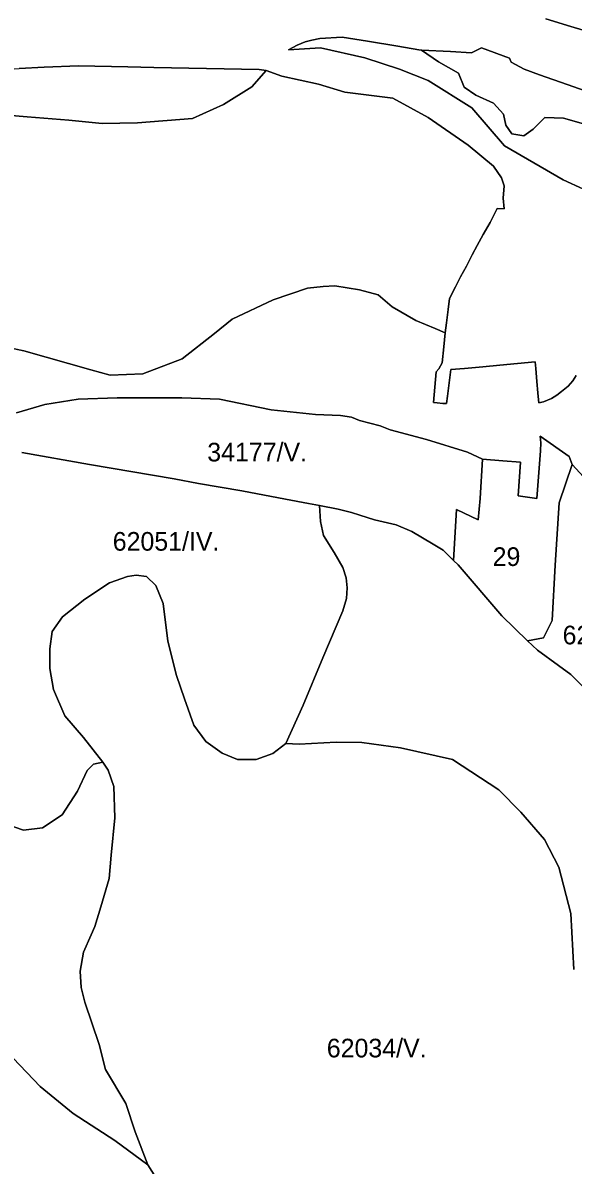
# Model space of a CAD drawing. Extents: x -521621 to -516761, y -1190184 to -1184927.
# Drawn here: x -519109 to -518666, y -1188092 to -1187173 of the extents above; entities that cross this region are included whole.
import ezdxf

# ---------------------------------------------------------------- set-up
doc = ezdxf.new("R2010")
doc.units = 0
doc.layers.add('BPEJ_s', color=7, linetype='Continuous')

msp = doc.modelspace()

# ---------------------------------------------------------------- linework, layer by layer
at = {"layer": 'BPEJ_s'}
for p, q in [((-518688.38, -1187169.96), (-518668.2, -1187176.14)), ((-518668.2, -1187176.14), (-518641.27, -1187184.22)), ((-518888.55, -1187191.16), (-518895.45, -1187195.01)), ((-518882.14, -1187188.59), (-518888.55, -1187191.16)), ((-518876.68, -1187187.14), (-518882.14, -1187188.59)), ((-518870.26, -1187186.02), (-518876.68, -1187187.14)), ((-518852.25, -1187184.81), (-518870.26, -1187186.02)), ((-518831.81, -1187188.13), (-518852.25, -1187184.81)), ((-518807.54, -1187191.97), (-518831.81, -1187188.13)), ((-518790.68, -1187195.03), (-518807.54, -1187191.97)), ((-518895.45, -1187195.01), (-518869.79, -1187193.48)), ((-518869.79, -1187193.48), (-518833.92, -1187201.34)), ((-518833.92, -1187201.34), (-518806.02, -1187210.57)), ((-518788.41, -1187195.16), (-518790.68, -1187195.03)), ((-518765.2, -1187196.45), (-518788.41, -1187195.16)), ((-518748.24, -1187197.55), (-518765.2, -1187196.45)), ((-518740.14, -1187193.42), (-518748.24, -1187197.55)), ((-518717.55, -1187201.72), (-518740.14, -1187193.42)), ((-518716.17, -1187205.03), (-518717.55, -1187201.72)), ((-519092.1, -1187208.96), (-519112.11, -1187210)), ((-519064.5, -1187207.92), (-519092.1, -1187208.96)), ((-519024.83, -1187208.61), (-519064.5, -1187207.92)), ((-519003.79, -1187209.3), (-519024.83, -1187208.61)), ((-518919.06, -1187210.79), (-519003.79, -1187209.3)), ((-518913.41, -1187211.72), (-518919.06, -1187210.79)), ((-518806.02, -1187210.57), (-518783.14, -1187219.65)), ((-518705.68, -1187210.59), (-518716.17, -1187205.03)), ((-518693.5, -1187215.16), (-518705.68, -1187210.59)), ((-518900.96, -1187216.19), (-518913.41, -1187211.72)), ((-518871.22, -1187222.51), (-518900.96, -1187216.19)), ((-518783.14, -1187219.65), (-518747.81, -1187241.68)), ((-518671.13, -1187222.76), (-518693.5, -1187215.16)), ((-518850.19, -1187229.14), (-518871.22, -1187222.51)), ((-518811.5, -1187233.85), (-518850.19, -1187229.14)), ((-518652.08, -1187229.66), (-518671.13, -1187222.76)), ((-518783.14, -1187249.42), (-518811.5, -1187233.85)), ((-518747.81, -1187241.68), (-518721.57, -1187272.27)), ((-518750.97, -1187271.58), (-518783.14, -1187249.42)), ((-518730.57, -1187288.54), (-518750.97, -1187271.58)), ((-518721.57, -1187272.27), (-518674.53, -1187299.62)), ((-518724.01, -1187297.86), (-518730.57, -1187288.54)), ((-518721.97, -1187304.42), (-518724.01, -1187297.86)), ((-518674.53, -1187299.62), (-518631.7, -1187319.15)), ((-518722.65, -1187314.38), (-518721.97, -1187304.42)), ((-518721.97, -1187322.97), (-518722.65, -1187314.38)), ((-518733.28, -1187333.83), (-518727.4, -1187322.52)), ((-518727.4, -1187322.52), (-518721.97, -1187322.97)), ((-518738.7, -1187343.45), (-518733.28, -1187333.83)), ((-518743.56, -1187352.5), (-518738.7, -1187343.45)), ((-518747.52, -1187359.86), (-518743.56, -1187352.5)), ((-518752.27, -1187369.02), (-518747.52, -1187359.86)), ((-518756.96, -1187377.73), (-518752.27, -1187369.02)), ((-518880.2, -1187386.72), (-518867.5, -1187385.44)), ((-518867.5, -1187385.44), (-518858.12, -1187384.95)), ((-518858.12, -1187384.95), (-518838.2, -1187388.01)), ((-518765.94, -1187395.16), (-518761.11, -1187385.61)), ((-518761.11, -1187385.61), (-518756.96, -1187377.73)), ((-518907.72, -1187396.04), (-518880.2, -1187386.72)), ((-518838.2, -1187388.01), (-518823.38, -1187392.1)), ((-518823.38, -1187392.1), (-518812.14, -1187401.82)), ((-518767.05, -1187404.01), (-518765.94, -1187395.16)), ((-518940.75, -1187411.71), (-518907.72, -1187396.04)), ((-518812.14, -1187401.82), (-518792.98, -1187412.81)), ((-518768.43, -1187414.67), (-518767.05, -1187404.01)), ((-518955.14, -1187423.15), (-518940.75, -1187411.71)), ((-518792.98, -1187412.81), (-518777.4, -1187419.2)), ((-519194.34, -1187419.33), (-519108.4, -1187437.13)), ((-518777.4, -1187419.2), (-518769.31, -1187422.77)), ((-518769.31, -1187422.77), (-518770.52, -1187434)), ((-518770.52, -1187434), (-518769.31, -1187422.77)), ((-518769.31, -1187422.77), (-518768.43, -1187414.67)), ((-518980.97, -1187443.48), (-518955.14, -1187423.15)), ((-519108.4, -1187437.13), (-519054.63, -1187452.38)), ((-518770.52, -1187434), (-518771.89, -1187446.71)), ((-518771.89, -1187446.71), (-518770.52, -1187434)), ((-519012.72, -1187455.77), (-518980.97, -1187443.48)), ((-518771.89, -1187446.71), (-518774.35, -1187451.49)), ((-518774.35, -1187451.49), (-518771.89, -1187446.71)), ((-518753.76, -1187451.33), (-518739.1, -1187450.04)), ((-518739.1, -1187450.04), (-518753.76, -1187451.33)), ((-518739.1, -1187450.04), (-518725.3, -1187448.74)), ((-518725.3, -1187448.74), (-518739.1, -1187450.04)), ((-518725.3, -1187448.74), (-518711.06, -1187447.23)), ((-518711.06, -1187447.23), (-518725.3, -1187448.74)), ((-518711.06, -1187447.23), (-518697.05, -1187445.94)), ((-518697.05, -1187445.94), (-518711.06, -1187447.23)), ((-518697.05, -1187445.94), (-518696.4, -1187451.33)), ((-518696.4, -1187451.33), (-518697.05, -1187445.94)), ((-519054.63, -1187452.38), (-519038.97, -1187456.61)), ((-519038.97, -1187456.61), (-519012.72, -1187455.77)), ((-518776.53, -1187454.09), (-518778.1, -1187472.56)), ((-518778.1, -1187472.56), (-518776.53, -1187454.09)), ((-518774.35, -1187451.49), (-518776.53, -1187454.09)), ((-518776.53, -1187454.09), (-518774.35, -1187451.49)), ((-518767.37, -1187473.68), (-518764.76, -1187452.19)), ((-518764.76, -1187452.19), (-518767.37, -1187473.68)), ((-518764.76, -1187452.19), (-518753.76, -1187451.33)), ((-518753.76, -1187451.33), (-518764.76, -1187452.19)), ((-518696.4, -1187451.33), (-518695.54, -1187461.69)), ((-518695.54, -1187461.69), (-518696.4, -1187451.33)), ((-518666.67, -1187461.38), (-518663.99, -1187456.89)), ((-518663.99, -1187456.89), (-518666.67, -1187461.38)), ((-518695.54, -1187461.69), (-518694.83, -1187470.9)), ((-518694.83, -1187470.9), (-518695.54, -1187461.69)), ((-518675.67, -1187469.94), (-518670.34, -1187465.49)), ((-518670.34, -1187465.49), (-518675.67, -1187469.94)), ((-518670.34, -1187465.49), (-518666.67, -1187461.38)), ((-518666.67, -1187461.38), (-518670.34, -1187465.49)), ((-519064.79, -1187476.1), (-519091.46, -1187480.34)), ((-519033.46, -1187474.83), (-519064.79, -1187476.1)), ((-518981.39, -1187474.83), (-519033.46, -1187474.83)), ((-518950.91, -1187476.1), (-518981.39, -1187474.83)), ((-518909.42, -1187484.57), (-518950.91, -1187476.1)), ((-518778.1, -1187472.56), (-518778.69, -1187478.57)), ((-518778.69, -1187478.57), (-518778.1, -1187472.56)), ((-518768.18, -1187479.55), (-518767.37, -1187473.68)), ((-518767.37, -1187473.68), (-518768.18, -1187479.55)), ((-518694.83, -1187470.9), (-518694.27, -1187476.5)), ((-518694.27, -1187476.5), (-518694.83, -1187470.9)), ((-518694.27, -1187476.5), (-518694.11, -1187479.1)), ((-518694.11, -1187479.1), (-518694.27, -1187476.5)), ((-518690.22, -1187478.05), (-518683.92, -1187475.56)), ((-518683.92, -1187475.56), (-518690.22, -1187478.05)), ((-518683.92, -1187475.56), (-518679.45, -1187472.72)), ((-518679.45, -1187472.72), (-518683.92, -1187475.56)), ((-518679.45, -1187472.72), (-518675.67, -1187469.94)), ((-518675.67, -1187469.94), (-518679.45, -1187472.72)), ((-519091.46, -1187480.34), (-519114.33, -1187487.11)), ((-518873.85, -1187488.39), (-518909.42, -1187484.57)), ((-518778.69, -1187478.57), (-518775.77, -1187478.95)), ((-518775.77, -1187478.95), (-518778.69, -1187478.57)), ((-518775.77, -1187478.95), (-518771.14, -1187479.48)), ((-518771.14, -1187479.48), (-518775.77, -1187478.95)), ((-518771.14, -1187479.48), (-518768.18, -1187479.55)), ((-518768.18, -1187479.55), (-518771.14, -1187479.48)), ((-518694.11, -1187479.1), (-518690.22, -1187478.05)), ((-518690.22, -1187478.05), (-518694.11, -1187479.1)), ((-518853.53, -1187489.23), (-518873.85, -1187488.39)), ((-518844.76, -1187490.58), (-518853.53, -1187489.23)), ((-518838.25, -1187493.19), (-518844.76, -1187490.58)), ((-518821.76, -1187497.54), (-518838.25, -1187493.19)), ((-518813.51, -1187500.79), (-518821.76, -1187497.54)), ((-518784.42, -1187508.4), (-518813.51, -1187500.79)), ((-518751.43, -1187518.6), (-518784.42, -1187508.4)), ((-518669.51, -1187522.14), (-518693.02, -1187505.72)), ((-518693.02, -1187505.72), (-518692.26, -1187511.17)), ((-518692.26, -1187511.17), (-518692.55, -1187517.7)), ((-518739.36, -1187524.31), (-518751.43, -1187518.6)), ((-518692.55, -1187517.7), (-518695.48, -1187556.05)), ((-518667.05, -1187528.51), (-518669.51, -1187522.14)), ((-518722.93, -1187525.73), (-518739.36, -1187524.31)), ((-518708.77, -1187526.58), (-518722.93, -1187525.73)), ((-518710.52, -1187553.79), (-518708.77, -1187526.58)), ((-518658.09, -1187538.38), (-518667.05, -1187528.51)), ((-518695.48, -1187556.05), (-518710.52, -1187553.79))]:
    msp.add_line(p, q, dxfattribs=at)
for points in [[(-518641.27, -1187184.22), (-518668.2, -1187176.14), (-518688.38, -1187169.96)], [(-519685.69, -1187175.9), (-519667.22, -1187182.03), (-519652.89, -1187186.47), (-519641.3, -1187189.2), (-519629.99, -1187191.18), (-519601.06, -1187195.24), (-519565.43, -1187200.37), (-519536.97, -1187203.2), (-519506.81, -1187204.71), (-519400, -1187209.9), (-519353.85, -1187209.13), (-519299.97, -1187210.03), (-519128.66, -1187211.03), (-519112.11, -1187210), (-519092.1, -1187208.96), (-519064.5, -1187207.92), (-519024.83, -1187208.61), (-519003.79, -1187209.3), (-518919.06, -1187210.79), (-518913.41, -1187211.72)], [(-518631.7, -1187319.15), (-518674.53, -1187299.62), (-518721.57, -1187272.27), (-518747.81, -1187241.68), (-518783.14, -1187219.65), (-518806.02, -1187210.57), (-518833.92, -1187201.34), (-518869.79, -1187193.48), (-518895.45, -1187195.01), (-518888.55, -1187191.16), (-518882.14, -1187188.59), (-518876.68, -1187187.14), (-518870.26, -1187186.02), (-518852.25, -1187184.81), (-518831.81, -1187188.13), (-518807.54, -1187191.97), (-518790.68, -1187195.03), (-518788.41, -1187195.16), (-518774.8, -1187204.76), (-518758.75, -1187213.65), (-518753.96, -1187224.93), (-518744.74, -1187231.43), (-518730.39, -1187237.92), (-518722.53, -1187246.81), (-518720.48, -1187255.7), (-518715.69, -1187262.54), (-518706.13, -1187264.25), (-518698.61, -1187258.78), (-518689.04, -1187249.55), (-518674.01, -1187249.89), (-518652.48, -1187256.04)], [(-518652.48, -1187256.04), (-518674.01, -1187249.89), (-518689.04, -1187249.55), (-518698.61, -1187258.78), (-518706.13, -1187264.25), (-518715.69, -1187262.54), (-518720.48, -1187255.7), (-518722.53, -1187246.81), (-518730.39, -1187237.92), (-518744.74, -1187231.43), (-518753.96, -1187224.93), (-518758.75, -1187213.65), (-518774.8, -1187204.76), (-518788.41, -1187195.16), (-518765.2, -1187196.45), (-518748.24, -1187197.55), (-518740.14, -1187193.42), (-518717.55, -1187201.72), (-518716.17, -1187205.03), (-518705.68, -1187210.59), (-518693.5, -1187215.16), (-518671.13, -1187222.76), (-518652.08, -1187229.66)], [(-519137.62, -1187246.1), (-519105.9, -1187248.79), (-519072.32, -1187251.67), (-519045.33, -1187254.35), (-519017.1, -1187253.73), (-518972.81, -1187250.23), (-518947.88, -1187239.1), (-518925.02, -1187224.67), (-518913.41, -1187211.72), (-518900.96, -1187216.19), (-518871.22, -1187222.51), (-518850.19, -1187229.14), (-518811.5, -1187233.85), (-518783.14, -1187249.42), (-518750.97, -1187271.58), (-518730.57, -1187288.54), (-518724.01, -1187297.86), (-518721.97, -1187304.42), (-518722.65, -1187314.38), (-518721.97, -1187322.97), (-518727.4, -1187322.52), (-518733.28, -1187333.83), (-518738.7, -1187343.45), (-518743.56, -1187352.5), (-518747.52, -1187359.86), (-518752.27, -1187369.02), (-518756.96, -1187377.73), (-518761.11, -1187385.61), (-518765.94, -1187395.16), (-518767.05, -1187404.01), (-518768.43, -1187414.67), (-518769.31, -1187422.77), (-518777.4, -1187419.2), (-518792.98, -1187412.81), (-518812.14, -1187401.82), (-518823.38, -1187392.1), (-518838.2, -1187388.01), (-518858.12, -1187384.95), (-518867.5, -1187385.44), (-518880.2, -1187386.72), (-518907.72, -1187396.04), (-518940.75, -1187411.71), (-518955.14, -1187423.15), (-518980.97, -1187443.48), (-519012.72, -1187455.77), (-519038.97, -1187456.61), (-519054.63, -1187452.38), (-519108.4, -1187437.13), (-519194.34, -1187419.33)], [(-518913.41, -1187211.72), (-518925.02, -1187224.67), (-518947.88, -1187239.1), (-518972.81, -1187250.23), (-519017.1, -1187253.73), (-519045.33, -1187254.35), (-519072.32, -1187251.67), (-519105.9, -1187248.79), (-519137.62, -1187246.1)], [(-519114.33, -1187487.11), (-519091.46, -1187480.34), (-519064.79, -1187476.1), (-519033.46, -1187474.83), (-518981.39, -1187474.83), (-518950.91, -1187476.1), (-518909.42, -1187484.57), (-518873.85, -1187488.39), (-518853.53, -1187489.23), (-518844.76, -1187490.58), (-518838.25, -1187493.19), (-518821.76, -1187497.54), (-518813.51, -1187500.79), (-518784.42, -1187508.4), (-518751.43, -1187518.6), (-518739.36, -1187524.31), (-518741.11, -1187555.8), (-518742.87, -1187573.2), (-518760.17, -1187564.67), (-518762.67, -1187605.82), (-518771.03, -1187597.6), (-518778.94, -1187592.67), (-518796.09, -1187582.5), (-518808.72, -1187577.04), (-518826.24, -1187573.01), (-518838.03, -1187569.42), (-518844.76, -1187567.25), (-518855.62, -1187564.43), (-518870.38, -1187561.6), (-518879.27, -1187559.87), (-518897.99, -1187556.59), (-518933.12, -1187549.81), (-518967.84, -1187543.88), (-518987.43, -1187540.18), (-519055.51, -1187528.45), (-519110.16, -1187518.97)], [(-519110.16, -1187518.97), (-519055.51, -1187528.45), (-518987.43, -1187540.18), (-518967.84, -1187543.88), (-518933.12, -1187549.81), (-518897.99, -1187556.59), (-518879.27, -1187559.87), (-518870.38, -1187561.6), (-518869.72, -1187574.42), (-518867.34, -1187585.71), (-518858.65, -1187599.39), (-518851.71, -1187611.56), (-518849.1, -1187619.81), (-518848.24, -1187627.84), (-518848.89, -1187636.32), (-518851.64, -1187646.3), (-518867.95, -1187683.98), (-518883.67, -1187722.25), (-518897.6, -1187753.11), (-518907.98, -1187761.12), (-518921.62, -1187765.87), (-518936.45, -1187765.87), (-518948.9, -1187760.82), (-518961.95, -1187751.33), (-518971.73, -1187738.28), (-518979.15, -1187717.21), (-518985.67, -1187698.22), (-518992.49, -1187670.63), (-518996.34, -1187640.36), (-519002.28, -1187625.83), (-519009.69, -1187618.71), (-519017.99, -1187617.52), (-519025.11, -1187618.71), (-519039.64, -1187623.75), (-519059.5, -1187636.8), (-519077.29, -1187651.05), (-519085.54, -1187662.92), (-519087.65, -1187676.9), (-519087.65, -1187692.57), (-519084.69, -1187709.52), (-519075.38, -1187730.7), (-519060.56, -1187748.07), (-519044.89, -1187767.98), (-519052.51, -1187769.67), (-519057.6, -1187774.76), (-519065.22, -1187791.28), (-519077.49, -1187810.34), (-519093.58, -1187820.93), (-519108.82, -1187822.63), (-519122.79, -1187817.97)], [(-518648.89, -1187716.63), (-518668.36, -1187697.39), (-518678.21, -1187690.17), (-518695.13, -1187677.93), (-518703.18, -1187670.52), (-518690.34, -1187668.12), (-518683.38, -1187654.19), (-518680.76, -1187609.53), (-518677.5, -1187559.44), (-518667.05, -1187528.51), (-518658.09, -1187538.38)], [(-518665.7, -1187934.84), (-518668.3, -1187889.66), (-518677.89, -1187852.5), (-518689.45, -1187830.25), (-518708.43, -1187808.3), (-518726.22, -1187790.2), (-518763.58, -1187765.87), (-518805.39, -1187756.37), (-518836.52, -1187752.22), (-518856.98, -1187751.92), (-518886.93, -1187753.41), (-518897.6, -1187753.11), (-518883.67, -1187722.25), (-518867.95, -1187683.98), (-518851.64, -1187646.3), (-518848.89, -1187636.32), (-518848.24, -1187627.84), (-518849.1, -1187619.81), (-518851.71, -1187611.56), (-518858.65, -1187599.39), (-518867.34, -1187585.71), (-518869.72, -1187574.42), (-518870.38, -1187561.6), (-518855.62, -1187564.43), (-518844.76, -1187567.25), (-518838.03, -1187569.42), (-518826.24, -1187573.01), (-518808.72, -1187577.04), (-518796.09, -1187582.5), (-518778.94, -1187592.67), (-518771.03, -1187597.6), (-518762.67, -1187605.82), (-518759, -1187609.21), (-518723.89, -1187650.3), (-518703.18, -1187670.52), (-518695.13, -1187677.93), (-518678.21, -1187690.17), (-518668.36, -1187697.39), (-518648.89, -1187716.63)], [(-518997.05, -1188110.14), (-519008.55, -1188091.89), (-519018.86, -1188065.31), (-519026.39, -1188042.7), (-519042.64, -1188015.33), (-519047.8, -1187995.09), (-519059.3, -1187960.98), (-519062.25, -1187949.29), (-519063.1, -1187936.16), (-519060.56, -1187920.91), (-519054.21, -1187906.93), (-519051.24, -1187900.15), (-519046.59, -1187884.48), (-519039.81, -1187861.6), (-519038.12, -1187842.96), (-519035.16, -1187812.88), (-519036, -1187787.47), (-519040.66, -1187774.33), (-519044.89, -1187767.98), (-519060.56, -1187748.07), (-519075.38, -1187730.7), (-519084.69, -1187709.52), (-519087.65, -1187692.57), (-519087.65, -1187676.9), (-519085.54, -1187662.92), (-519077.29, -1187651.05), (-519059.5, -1187636.8), (-519039.64, -1187623.75), (-519025.11, -1187618.71), (-519017.99, -1187617.52), (-519009.69, -1187618.71), (-519002.28, -1187625.83), (-518996.34, -1187640.36), (-518992.49, -1187670.63), (-518985.67, -1187698.22), (-518979.15, -1187717.21), (-518971.73, -1187738.28), (-518961.95, -1187751.33), (-518948.9, -1187760.82), (-518936.45, -1187765.87), (-518921.62, -1187765.87), (-518907.98, -1187761.12), (-518897.6, -1187753.11), (-518886.93, -1187753.41), (-518856.98, -1187751.92), (-518836.52, -1187752.22), (-518805.39, -1187756.37), (-518763.58, -1187765.87), (-518726.22, -1187790.2), (-518708.43, -1187808.3), (-518689.45, -1187830.25), (-518677.89, -1187852.5), (-518668.3, -1187889.66), (-518665.7, -1187934.84)], [(-519122.79, -1187817.97), (-519108.82, -1187822.63), (-519093.58, -1187820.93), (-519077.49, -1187810.34), (-519065.22, -1187791.28), (-519057.6, -1187774.76), (-519052.51, -1187769.67), (-519044.89, -1187767.98), (-519040.66, -1187774.33), (-519036, -1187787.47), (-519035.16, -1187812.88), (-519038.12, -1187842.96), (-519039.81, -1187861.6), (-519046.59, -1187884.48), (-519051.24, -1187900.15), (-519054.21, -1187906.93), (-519060.56, -1187920.91), (-519063.1, -1187936.16), (-519062.25, -1187949.29), (-519059.3, -1187960.98), (-519047.8, -1187995.09), (-519042.64, -1188015.33), (-519026.39, -1188042.7), (-519018.86, -1188065.31), (-519008.55, -1188091.89), (-519035.11, -1188072.46), (-519068.81, -1188050.64), (-519095.38, -1188028.82), (-519117.18, -1188006.2)], [(-519117.18, -1188006.2), (-519095.38, -1188028.82), (-519068.81, -1188050.64), (-519035.11, -1188072.46), (-519008.55, -1188091.89), (-518997.05, -1188110.14)]]:
    msp.add_lwpolyline(points, dxfattribs=at)
msp.add_lwpolyline([(-518762.67, -1187605.82), (-518760.17, -1187564.67), (-518742.87, -1187573.2), (-518741.11, -1187555.8), (-518739.36, -1187524.31), (-518722.93, -1187525.73), (-518708.77, -1187526.58), (-518710.52, -1187553.79), (-518695.48, -1187556.05), (-518692.55, -1187517.7), (-518692.26, -1187511.17), (-518693.02, -1187505.72), (-518669.51, -1187522.14), (-518667.05, -1187528.51), (-518677.5, -1187559.44), (-518680.76, -1187609.53), (-518683.38, -1187654.19), (-518690.34, -1187668.12), (-518703.18, -1187670.52), (-518723.89, -1187650.3), (-518759, -1187609.21)], close=True, dxfattribs=at)

# ---------------------------------------------------------------- texts
for s, p in [('34177/V.', (-518960.86, -1187526.11)), ('62051/IV.', (-519036.92, -1187597.9)), ('29', (-518731.15, -1187610.19)), ('62051/IV.', (-518674.85, -1187673.25)), ('62034/V.', (-518864.64, -1188005.52))]:
    msp.add_text(s, height=15, dxfattribs=at).set_placement(p)

doc.saveas('drawing.dxf')
